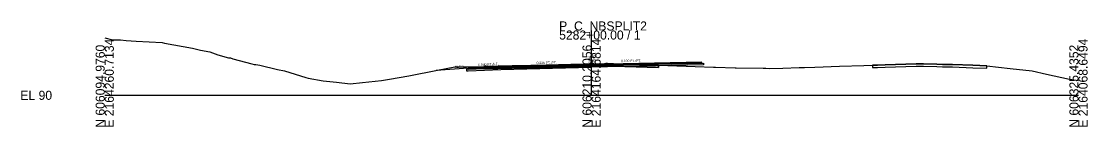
# Model space of a CAD drawing. Extents: x -26 to 1303, y -10 to 12038.
# Drawn here: x -25.7 to 302.8, y 1490.3 to 1522.8 of the extents above; entities that cross this region are included whole.
import ezdxf

# ---------------------------------------------------------------- set-up
doc = ezdxf.new("R2010")
doc.units = 0
for name, color, linetype in [('RD_GPK_XS_Cell', 7, 'Continuous'), ('RD_XS_Base', 7, 'Continuous'), ('RD_XS_ExGround', 7, 'Continuous'), ('RD_XS_ExPaveRet', 7, 'Continuous'), ('RD_XS_Pave', 7, 'Continuous'), ('RD_XS_PaveOvlay_CP', 7, 'Continuous'), ('RD_XS_TieSlope', 7, 'Continuous'), ('RD_XS_TX_Elev_EX', 7, 'Continuous'), ('RD_XS_TX_Elev_PR', 7, 'Continuous'), ('RD_XS_TX_ShdSlope', 7, 'Continuous'), ('RD_XS_TX_Slope', 7, 'Continuous')]:
    doc.layers.add(name, color=color, linetype=linetype)

msp = doc.modelspace()

# ---------------------------------------------------------------- linework, layer by layer
at = {"layer": 'RD_GPK_XS_Cell'}
for p, q in [((150, 1500), (150, 1520)), ((0, 1500), (150, 1500)), ((150, 1500), (300, 1500))]:
    msp.add_line(p, q, dxfattribs=at)
at = {"layer": 'RD_XS_Base'}
for p, q in [((112, 1508.09), (111.5, 1508.07)), ((111.5, 1508.07), (111.5, 1508.07)), ((111.5, 1508.07), (111.5, 1507.57)), ((122, 1508.49), (112, 1508.09)), ((112, 1508.09), (112, 1508.09)), ((112, 1507.59), (122, 1507.99)), ((150, 1509.19), (122, 1508.49)), ((122, 1507.99), (150, 1508.69)), ((122, 1508.49), (122, 1508.49)), ((122, 1507.99), (122, 1507.99)), ((150, 1509.19), (184, 1509.87)), ((184.5, 1509.38), (150, 1508.69)), ((150, 1508.69), (150, 1509.35)), ((150, 1509.35), (150, 1509.35)), ((150, 1509.35), (150, 1509.35)), ((150, 1509.35), (150, 1509.19)), ((150, 1509.19), (150, 1509.19)), ((150, 1508.69), (150, 1509.19)), ((150, 1509.19), (150, 1509.19)), ((150, 1509.19), (150, 1509.19)), ((150, 1508.69), (150, 1508.69)), ((174, 1509.67), (174, 1509.67)), ((174, 1509.67), (174, 1509.67)), ((174, 1509.17), (174, 1509.17)), ((174, 1509.17), (174, 1509.17)), ((184, 1509.87), (184, 1509.87)), ((184.5, 1509.88), (184.5, 1509.38)), ((184.5, 1509.85), (184.5, 1509.85)), ((111.5, 1507.57), (112, 1507.59)), ((112, 1507.59), (112, 1507.59))]:
    msp.add_line(p, q, dxfattribs=at)
at = {"layer": 'RD_XS_ExGround'}
msp.add_lwpolyline([(0, 1517.71), (2.4, 1517.14), (4.86, 1517.09), (6.56, 1516.96), (9.7, 1516.68), (17.68, 1516.28), (18.45, 1516.13), (27.07, 1514.51), (29.54, 1513.97), (32.35, 1513.39), (34.87, 1512.53), (38.11, 1511.56), (38.74, 1511.55), (39.49, 1511.26), (45.3, 1509.68), (46, 1509.53), (46.54, 1509.5), (47.8, 1509.35), (53.21, 1507.99), (55.38, 1507.54), (62.01, 1505.5), (62.63, 1505.31), (67.31, 1504.49), (71.42, 1504.03), (75.61, 1503.5), (79.45, 1503.91), (85.29, 1504.52), (87.74, 1504.97), (93.68, 1506.05), (102.57, 1507.71), (107.91, 1508.74), (111.44, 1508.77), (116.78, 1508.93), (125.54, 1509.08), (131.32, 1509.18), (135.98, 1509.33), (139.79, 1509.44), (143.56, 1509.5), (145.23, 1509.49), (149.2, 1509.64), (153.93, 1509.76), (154.44, 1509.77), (154.93, 1509.77), (156.66, 1509.74), (156.66, 1509.74), (156.76, 1509.73), (170.62, 1509.28), (187.55, 1508.69), (187.95, 1508.68), (188.13, 1508.67), (194.19, 1508.49), (194.38, 1508.49), (194.57, 1508.48), (202.86, 1508.33), (203.7, 1508.34), (204.73, 1508.32), (208.92, 1508.38), (213.92, 1508.54), (215.13, 1508.59), (215.64, 1508.62), (218.73, 1508.67), (226.36, 1508.97), (233.83, 1509.23), (236.55, 1509.32), (238.13, 1509.35), (240.46, 1509.44), (249.97, 1509.73), (251.13, 1509.75), (252.29, 1509.74), (256.36, 1509.62), (258.13, 1509.55), (260.31, 1509.5), (261.15, 1509.5), (267.44, 1509.27), (271.79, 1509.08), (278.98, 1508.31), (285.76, 1507.53), (290.13, 1506.53), (294.91, 1505.49), (297.19, 1505.02), (300, 1504.53)], dxfattribs=at)
at = {"layer": 'RD_XS_ExPaveRet'}
for points in [[(170.62, 1509.28), (170.62, 1509.28), (170.62, 1509.28), (170.62, 1508.53), (170.62, 1508.53), (156.76, 1508.98), (156.76, 1508.98), (156.66, 1508.99), (156.66, 1508.99), (156.66, 1508.99), (154.93, 1509.02), (154.93, 1509.02), (154.93, 1509.02), (154.93, 1509.02), (154.44, 1509.02), (153.93, 1509.01), (149.2, 1508.89), (149.2, 1508.89), (145.23, 1508.74), (145.23, 1508.74), (143.56, 1508.75), (143.56, 1508.75), (139.79, 1508.69), (139.79, 1508.69), (135.98, 1508.58), (135.98, 1508.58), (135.98, 1508.58), (131.32, 1508.43), (125.54, 1508.33), (125.54, 1508.33), (116.78, 1508.18), (116.78, 1508.18), (116.78, 1508.18), (116.78, 1508.93), (116.78, 1508.93), (116.78, 1508.93), (116.78, 1508.93), (125.54, 1509.08), (125.54, 1509.08), (131.32, 1509.18), (135.98, 1509.33), (135.98, 1509.33), (135.98, 1509.33), (139.79, 1509.44), (139.79, 1509.44), (143.56, 1509.5), (143.56, 1509.5), (145.23, 1509.49), (145.23, 1509.49), (149.2, 1509.64), (149.2, 1509.64), (153.93, 1509.76), (154.44, 1509.77), (154.93, 1509.77), (154.93, 1509.77), (154.93, 1509.77), (154.93, 1509.77), (156.66, 1509.74), (156.66, 1509.74), (156.66, 1509.74), (156.76, 1509.73), (156.76, 1509.73), (170.62, 1509.28)], [(156.76, 1509.73), (156.66, 1509.74), (156.66, 1509.74), (154.93, 1509.77), (154.44, 1509.77), (153.93, 1509.76), (149.2, 1509.64), (145.23, 1509.49), (143.56, 1509.5), (139.79, 1509.44), (135.98, 1509.33), (131.32, 1509.18), (125.54, 1509.08), (116.78, 1508.93), (116.78, 1508.93), (116.78, 1508.18), (116.78, 1508.18), (125.54, 1508.33), (131.32, 1508.43), (135.98, 1508.58), (139.79, 1508.69), (143.56, 1508.75), (145.23, 1508.74), (149.2, 1508.89), (153.93, 1509.01), (154.44, 1509.02), (154.93, 1509.02), (156.66, 1508.99), (156.66, 1508.99), (156.76, 1508.98), (170.62, 1508.53), (170.62, 1509.28), (156.76, 1509.73)], [(271.79, 1509.08), (267.44, 1509.27), (267.44, 1509.27), (261.15, 1509.5), (261.15, 1509.5), (260.31, 1509.5), (260.31, 1509.5), (258.13, 1509.55), (258.13, 1509.55), (256.36, 1509.62), (256.36, 1509.62), (252.29, 1509.74), (251.13, 1509.75), (251.13, 1509.75), (249.97, 1509.73), (249.97, 1509.73), (249.97, 1509.73), (240.46, 1509.44), (240.46, 1509.44), (238.13, 1509.35), (238.13, 1509.35), (236.55, 1509.32), (236.55, 1509.32), (236.55, 1509.32), (236.55, 1508.57), (236.55, 1508.57), (238.13, 1508.6), (238.13, 1508.6), (240.46, 1508.69), (240.46, 1508.69), (249.97, 1508.98), (249.97, 1508.98), (249.97, 1508.98), (251.13, 1509), (251.13, 1509), (252.29, 1508.99), (256.36, 1508.87), (256.36, 1508.87), (258.13, 1508.8), (258.13, 1508.8), (260.31, 1508.75), (260.31, 1508.75), (261.15, 1508.75), (261.15, 1508.75), (267.44, 1508.52), (267.44, 1508.52), (271.79, 1508.33), (271.79, 1508.33), (271.79, 1508.33), (271.79, 1509.08), (271.79, 1509.08), (271.79, 1509.08), (271.79, 1509.08)], [(271.79, 1509.08), (267.44, 1509.27), (261.15, 1509.5), (260.31, 1509.5), (258.13, 1509.55), (256.36, 1509.62), (252.29, 1509.74), (251.13, 1509.75), (249.97, 1509.73), (240.46, 1509.44), (238.13, 1509.35), (236.55, 1509.32), (236.55, 1509.32), (236.55, 1508.57), (236.55, 1508.57), (238.13, 1508.6), (240.46, 1508.69), (249.97, 1508.98), (251.13, 1509), (252.29, 1508.99), (256.36, 1508.87), (258.13, 1508.8), (260.31, 1508.75), (261.15, 1508.75), (267.44, 1508.52), (271.79, 1508.33), (271.79, 1509.08)]]:
    msp.add_lwpolyline(points, dxfattribs=at)
at = {"layer": 'RD_XS_Pave'}
for p, q in [((122, 1508.81), (112, 1508.41)), ((122, 1508.65), (112, 1508.25)), ((112, 1508.25), (122, 1508.65)), ((112, 1508.09), (122, 1508.49)), ((112, 1508.41), (112, 1508.41)), ((112, 1508.41), (112, 1508.25)), ((112, 1508.25), (112, 1508.25)), ((112, 1508.25), (112, 1508.09)), ((150, 1509.51), (122, 1508.81)), ((150, 1509.35), (122, 1508.65)), ((122, 1508.65), (150, 1509.35)), ((122, 1508.49), (150, 1509.19)), ((122, 1508.81), (122, 1508.81)), ((122, 1508.65), (122, 1508.65)), ((122, 1508.65), (122, 1508.65)), ((122, 1508.49), (122, 1508.49)), ((184, 1510.19), (150, 1509.51)), ((184, 1510.03), (150, 1509.35)), ((150, 1509.35), (184, 1510.03)), ((150, 1509.19), (184.5, 1509.88)), ((150, 1509.51), (150, 1509.51)), ((150, 1509.19), (150, 1509.35)), ((150, 1509.35), (150, 1509.35)), ((150, 1509.35), (150, 1509.35)), ((150, 1509.35), (150, 1509.35)), ((150, 1509.35), (150, 1509.35)), ((150, 1509.35), (150, 1509.19)), ((150, 1509.35), (150, 1509.35)), ((150, 1509.19), (150, 1509.19)), ((150, 1509.19), (150, 1509.19)), ((174, 1509.99), (174, 1509.99)), ((174, 1509.99), (174, 1509.99)), ((174, 1509.83), (174, 1509.83)), ((174, 1509.83), (174, 1509.83)), ((174, 1509.83), (174, 1509.83)), ((174, 1509.83), (174, 1509.83)), ((174, 1509.67), (174, 1509.67)), ((174, 1509.67), (174, 1509.67)), ((184, 1510.03), (184, 1510.19)), ((184, 1510.19), (184, 1510.19)), ((184, 1509.87), (184, 1510.03)), ((184, 1510.03), (184, 1510.03))]:
    msp.add_line(p, q, dxfattribs=at)
at = {"layer": 'RD_XS_PaveOvlay_CP'}
for p, q in [((122, 1508.81), (112, 1508.41)), ((150, 1509.51), (122, 1508.81)), ((122, 1508.81), (122, 1508.81)), ((184, 1510.19), (150, 1509.51)), ((150, 1509.51), (150, 1509.51)), ((174, 1509.99), (174, 1509.99)), ((174, 1509.99), (174, 1509.99))]:
    msp.add_line(p, q, dxfattribs=at)
at = {"layer": 'RD_XS_TieSlope'}
msp.add_line((112, 1508.41), (102.12, 1507.62), dxfattribs=at)

# ---------------------------------------------------------------- texts
at = {"layer": 'RD_GPK_XS_Cell'}
for s, p in [('P_C_NBSPLIT2', (140, 1520)), ('5282+00.00 / 1', (140, 1517.2)), ('EL 90', (-26, 1498.6))]:
    msp.add_text(s, height=2.8, dxfattribs=at).set_placement(p)
for s, p in [('N 606094.9760', (0, 1490)), ('E 2164260.7134', (2.8, 1490)), ('N 606210.2056', (150, 1490)), ('E 2164164.6814', (152.8, 1490)), ('N 606325.4352', (300, 1490)), ('E 2164068.6494', (302.8, 1490))]:
    msp.add_text(s, height=2.8, rotation=90, dxfattribs=at).set_placement(p)
at = {"layer": 'RD_XS_TX_Elev_EX'}
msp.add_text('99.65', height=0.6, rotation=90, dxfattribs=at).set_placement((149.71, 1510))
at = {"layer": 'RD_XS_TX_Elev_PR'}
msp.add_text('99.51', height=1, rotation=90, dxfattribs=at).set_placement((151.25, 1509.82))
at = {"layer": 'RD_XS_TX_ShdSlope'}
msp.add_text('12.5:1', height=0.75, rotation=4.5739, dxfattribs=at).set_placement((107.83, 1508.36))
at = {"layer": 'RD_XS_TX_Slope'}
for s, rotation, p in [('0.040 FT./FT.', 2.2906, (115.05, 1509.05)), ('0.025 FT./FT.', 1.4321, (133.06, 1509.61)), ('0.020 FT./FT.', 1.1458, (159.06, 1510.21))]:
    msp.add_text(s, height=0.75, rotation=rotation, dxfattribs=at).set_placement(p)

doc.saveas('drawing.dxf')
